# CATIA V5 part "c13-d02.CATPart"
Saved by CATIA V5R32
Part number: Part1
Bounding box of the stored display mesh (mm): x -33 to 33, y -200.819 to 48, z -35 to 35
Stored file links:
  D:\PROJECTS\Project 2022\CATIA V5 6R 2022\Resources\Part Files\c13_catia_v5_6r2022_prt\c13_catia_v5-6r2022_figr_13-12\c13-d02.CATPart
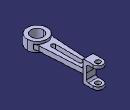
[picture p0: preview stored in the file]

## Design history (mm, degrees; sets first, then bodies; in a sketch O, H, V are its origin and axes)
Body1 (main body)
  Sketch1 on yz-plane, origin (0, 0, 0), H (0, 1, 0), V (0, 0, 1)
    line L1 (0, 0) -> (0, -35)
    point P1 (0, -35)
    line L2 (0, -35) -> (48, -35)
    point P2 (48, -35)
    line L3 (48, -35) -> (48, -25)
    point P3 (48, -25)
    line L4 (48, -25) -> (10, -25)
    point P4 (10, -25)
    line L5 (10, -25) -> (10, 0)
    point P5 (10, 0)
    point P6 (0, 0)
    point P7 (0, 0)
    point P8 (0, 35)
    point P9 (48, 35)
    point P10 (48, 25)
    point P11 (10, 25)
    point P12 (10, 0)
    point P13 (0, 0)
    line L6 (0, 0) -> (0, 35)
    line L7 (0, 35) -> (48, 35)
    line L8 (48, 35) -> (48, 25)
    line L9 (48, 25) -> (10, 25)
    line L10 (10, 25) -> (10, 0)
    length L8 = 10
    distance P3 L9 = 50
    length L2 = 48
    distance L10 L6 = 10
    vertical: L1 V, L3 V, L5 V
    horizontal: L2 H, L4 H
    symmetry: O P7 H, P1 P8 H, P2 P9 H, P3 P10 H, P4 P11 H, P5 P12 H, P6 P13 H, L1 L6 H, L2 L7 H, L3 L8 H, L4 L9 H, L5 L10 H
    coincidence: P13 P7, P12 P5, P6 P7
  Pad1: profile Sketch1, direction (1, 0, 0), length 16, mirrored extent
  Sketch2 on xy-plane, origin (0, 0, 0), H (1, 0, 0), V (0, 1, 0)
    circle A1 centre (0, -168) radius 33
    point P1 (0, -168)
    circle A2 centre (0, -168) radius 20
    distance P1 H = 168
    radius A1 = 33
    radius A2 = 20
    coincidence: P1 V
  Pad2: profile Sketch2, direction (0, 0, 1), length 16, mirrored extent
  Sketch3 on xy-plane, origin (0, 0, 0), H (1, 0, 0), V (0, 1, 0)
    line L1 (-16, 0) -> (-25, -146.4593)
    point P1 (-16, 0)
    point P2 (-25, -146.4593)
    line L2 (16, 0) -> (25, -146.4593)
    point P3 (16, 0)
    point P4 (25, -146.4593)
    reference projected line E1 (16, 48) -> (16, 0) from edge [face of Pad1 | face of Pad1]
    reference projected line E2 (-16, 48) -> (-16, 0) from edge [face of Pad1 | face of Pad1]
    projected circle E3 centre (0, -168) radius 33 from edge [face of Pad2 | face of Pad2]
    projected arc E4 centre (0, -168) radius 33 from (25, -146.4593) to (-25, -146.4593) ccw from edge [face of Pad2 | face of Pad2]
    line L3 (-16, 0) -> (16, 0)
    distance P4 P2 H = 50
    coincidence: P1 H, P3 H, P3 E1, P1 E2, P2 E3, P4 E3
    symmetry: P4 P2 V
    horizontal: L3 H
  Pad3: profile Sketch3, direction (0, 0, 1), length 8, mirrored extent
  Fillet1: radius 6, on edge [face of Pad1 | face of Pad3]; edge [face of Pad3 | face of Pad1]; edge [face of Pad1 | face of Pad1] (x2)
  Fillet2: radius 30, on edge [face of Pad3 | face of Pad2]; edge [face of Pad2 | face of Pad3]
  TritangentFillet1: Face1 face of Pad1, Face2 face of Pad1, RemoveFace face of Pad1
  TritangentFillet2: Face1 face of Pad1, Face2 face of Pad1, RemoveFace face of Pad1
  Sketch4 on face of Pad1, origin (2.8418, 32, 35), H (1, 0, 0), V (0, 1, 0)
    point P1 (-2.8418, 0)
    reference projected arc E1 centre (-2.8418, 0) radius 16 from (13.1582, 0) to (-18.8418, 0) ccw from edge [face of Pad1 | face of TritangentFillet1]
    concentricity: P1 E1
  Hole1: placed by Sketch4, at (0, 32, 35) direction (0, 0, -1), diameter 16, through (limit type 3)
  Sketch5 on face of Pad3, origin (0, 0, 8), H (1, 0, 0), V (0, 1, 0)
    construction line L1 (0, -25) -> (0, -115)
    point P1 (0, -25)
    line L2 (7, -25) -> (7, -115)
    line L3 (-7, -115) -> (-7, -25)
    arc A1 centre (0, -115) radius 7 from (7, -115) to (-7, -115) cw
    arc A2 centre (0, -25) radius 7 from (-7, -25) to (7, -25) cw
    distance P1 H = 25
    length L1 = 90
    radius A1 = 7
    coincidence: P1 V
    vertical: L1 V
    tangency: A1 L2, A2 L2, A1 L3, A2 L3
    parallelism: L1 L2
  Pocket1: profile Sketch5, direction (0, 0, -1), through (limit type 3)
